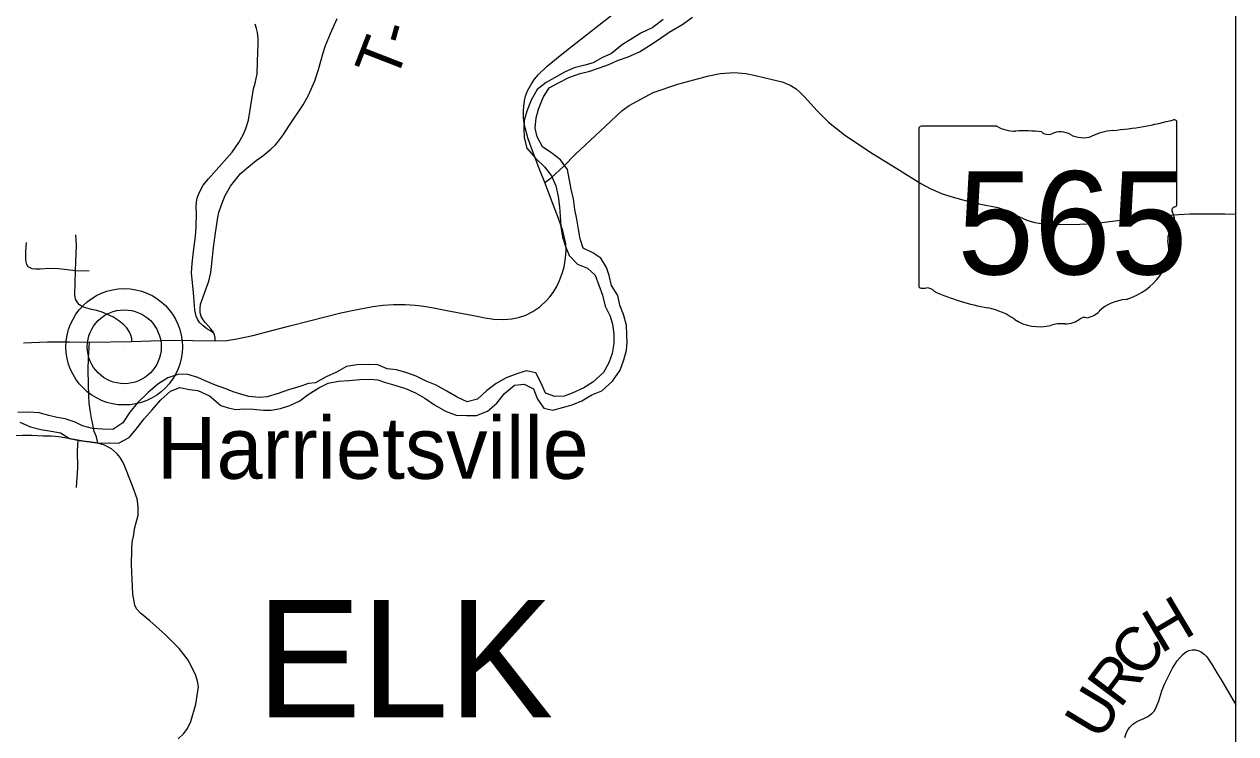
# Model space of a CAD drawing. Extents: x -10.5 to 40.6, y -3.2 to 22.
# Drawn here: x -5.292 to -3.744, y 19.035 to 19.942 of the extents above; entities that cross this region are included whole.
import ezdxf

# ---------------------------------------------------------------- set-up
doc = ezdxf.new("R2010")
doc.units = 0
for name, color, linetype in [('GM_X_County_Road', 7, 'Continuous'), ('GM_X_Major_River', 7, 'Continuous'), ('GM_X_State_Route', 7, 'Continuous'), ('GM_X_State_Shield', 7, 'Continuous'), ('GM_X_Township_Road', 7, 'Continuous'), ('GM_X_Township_Road_Text', 7, 'Continuous'), ('GM_X_Township_Text', 7, 'Continuous'), ('GM_X_Unincorporated', 7, 'Continuous'), ('GM_X_Unincorporated_Location', 7, 'Continuous'), ('GM_X_Unincorporated_Text', 7, 'Continuous')]:
    doc.layers.add(name, color=color, linetype=linetype)

msp = doc.modelspace()

# ---------------------------------------------------------------- linework, layer by layer
at = {"layer": 'GM_X_County_Road'}
msp.add_lwpolyline([(-5.0953, 19.0288), (-5.0879, 19.0354), (-5.0834, 19.042), (-5.0792, 19.0508), (-5.0727, 19.073), (-5.0694, 19.0953), (-5.0706, 19.1026), (-5.0727, 19.1098), (-5.0819, 19.1289), (-5.0941, 19.1444), (-5.1113, 19.1615), (-5.1316, 19.1794), (-5.1434, 19.1892), (-5.1486, 19.1948), (-5.1506, 19.1994), (-5.1532, 19.2136), (-5.1549, 19.2512), (-5.1546, 19.2707), (-5.1539, 19.2797), (-5.1519, 19.2898), (-5.1508, 19.2971), (-5.148, 19.3082), (-5.1462, 19.3147), (-5.1464, 19.3257), (-5.1476, 19.3356), (-5.1532, 19.3508), (-5.1618, 19.3725), (-5.165, 19.3809), (-5.1692, 19.3881), (-5.1733, 19.3931), (-5.1802, 19.3993), (-5.1893, 19.404), (-5.1978, 19.4066), (-5.1996, 19.4145), (-5.2023, 19.4214), (-5.2046, 19.4324), (-5.206, 19.4386), (-5.2078, 19.4485), (-5.2088, 19.4575), (-5.2094, 19.4669), (-5.2098, 19.4821), (-5.2103, 19.5004), (-5.2098, 19.5151), (-5.2086, 19.5357)], dxfattribs=at)
at = {"layer": 'GM_X_Major_River'}
for points in [[(-4.476, 19.9478), (-4.4891, 19.9378), (-4.5042, 19.9304), (-4.5181, 19.9219), (-4.5279, 19.9157), (-4.5418, 19.9042), (-4.5542, 19.8988), (-4.5651, 19.8926), (-4.5757, 19.8894), (-4.5896, 19.8859), (-4.602, 19.8804), (-4.6118, 19.875), (-4.6254, 19.8673), (-4.6366, 19.8585), (-4.6444, 19.8447), (-4.6499, 19.8306), (-4.6532, 19.8188), (-4.6539, 19.8086), (-4.6534, 19.7968), (-4.6498, 19.7836), (-4.6387, 19.7705), (-4.6272, 19.7596), (-4.6184, 19.7479), (-4.6129, 19.7351), (-4.6098, 19.7218), (-4.6081, 19.7086), (-4.6072, 19.6965), (-4.6063, 19.6832), (-4.6043, 19.6699), (-4.6004, 19.6578), (-4.5957, 19.6461), (-4.5854, 19.6352), (-4.5724, 19.6301), (-4.5625, 19.6211), (-4.5578, 19.6082), (-4.5531, 19.5958), (-4.55, 19.5814), (-4.5434, 19.5689), (-4.5406, 19.5587), (-4.5386, 19.5462), (-4.5388, 19.5337), (-4.541, 19.5212)], [(-4.5447, 19.6209), (-4.5482, 19.6311), (-4.5556, 19.6431), (-4.5658, 19.6499), (-4.578, 19.6558), (-4.5816, 19.6675), (-4.584, 19.68), (-4.586, 19.6929), (-4.5888, 19.705), (-4.5904, 19.7186), (-4.5932, 19.7311), (-4.598, 19.7561), (-4.6069, 19.7685), (-4.6179, 19.7771), (-4.6301, 19.7853), (-4.6367, 19.7978), (-4.6391, 19.8091), (-4.6381, 19.822), (-4.6352, 19.8334), (-4.6289, 19.8483), (-4.6215, 19.8605), (-4.6095, 19.8667), (-4.5963, 19.8737), (-4.5816, 19.8788), (-4.5695, 19.8819), (-4.5571, 19.8862), (-4.545, 19.8905), (-4.5341, 19.8956), (-4.5205, 19.9003), (-4.5062, 19.9065), (-4.4934, 19.9146), (-4.4822, 19.9219), (-4.4683, 19.9315), (-4.4521, 19.9412), (-4.4382, 19.9508)], [(-5.2973, 19.4332), (-5.2839, 19.4272), (-5.2707, 19.424), (-5.2574, 19.4218), (-5.2456, 19.4197), (-5.2338, 19.4126), (-5.2217, 19.4101), (-5.2084, 19.4083), (-5.1963, 19.4065), (-5.1842, 19.407), (-5.1713, 19.4064), (-5.1578, 19.4138), (-5.1488, 19.4245), (-5.1387, 19.4375), (-5.1283, 19.449), (-5.1174, 19.462), (-5.1051, 19.4731), (-5.093, 19.4778), (-5.0809, 19.4753), (-5.0699, 19.4739), (-5.0551, 19.4668), (-5.0409, 19.4548), (-5.0314, 19.4515), (-5.0216, 19.4494), (-5.0114, 19.4506), (-4.9989, 19.45), (-4.9864, 19.4486), (-4.9765, 19.4487), (-4.9644, 19.4507), (-4.9524, 19.4546), (-4.9399, 19.4605), (-4.9294, 19.4685), (-4.9155, 19.4774), (-4.9035, 19.4832), (-4.8906, 19.4856), (-4.8774, 19.4865), (-4.863, 19.4878), (-4.8498, 19.4883), (-4.8403, 19.4873), (-4.8305, 19.484), (-4.8183, 19.4807), (-4.805, 19.4763), (-4.7921, 19.4707), (-4.7803, 19.464), (-4.7677, 19.4555), (-4.754, 19.4476), (-4.7403, 19.4425), (-4.7271, 19.4418), (-4.7142, 19.442), (-4.7003, 19.4474), (-4.6883, 19.4578), (-4.6786, 19.47), (-4.6658, 19.4808), (-4.6533, 19.4821), (-4.6412, 19.4761), (-4.6365, 19.4629), (-4.6284, 19.4512), (-4.6166, 19.4487), (-4.6042, 19.4519), (-4.5921, 19.4554), (-4.5797, 19.4605), (-4.5669, 19.4682), (-4.5541, 19.4736), (-4.5406, 19.4859), (-4.5309, 19.5), (-4.5261, 19.513), (-4.5225, 19.5255), (-4.5218, 19.535), (-4.5223, 19.5445), (-4.5228, 19.5574), (-4.5264, 19.571), (-4.5311, 19.5827), (-4.5338, 19.5952), (-4.5416, 19.608), (-4.5447, 19.6209)], [(-4.541, 19.5212), (-4.545, 19.509), (-4.5521, 19.4968), (-4.5656, 19.4845), (-4.5772, 19.4772), (-4.5919, 19.4706), (-4.6021, 19.4667), (-4.6142, 19.4662), (-4.626, 19.4706), (-4.6314, 19.4834), (-4.6383, 19.4966), (-4.6509, 19.4988), (-4.6629, 19.4949), (-4.6765, 19.4898), (-4.6889, 19.4828), (-4.7009, 19.474), (-4.7129, 19.4629), (-4.7261, 19.4593), (-4.739, 19.4652), (-4.752, 19.4731), (-4.7657, 19.4805), (-4.7786, 19.4857), (-4.7912, 19.492), (-4.8033, 19.4964), (-4.8163, 19.5004), (-4.8284, 19.5015), (-4.8402, 19.5066), (-4.8527, 19.5069), (-4.867, 19.5064), (-4.8802, 19.5043), (-4.893, 19.4974), (-4.9062, 19.4912), (-4.9198, 19.4838), (-4.9288, 19.4826), (-4.9409, 19.4783), (-4.9541, 19.4747), (-4.9673, 19.47), (-4.9816, 19.4657), (-4.9915, 19.4648), (-5.0051, 19.4662), (-5.0153, 19.4691), (-5.0248, 19.4721), (-5.0343, 19.4758), (-5.0476, 19.4806), (-5.0606, 19.4861), (-5.0701, 19.4906), (-5.083, 19.4942), (-5.0943, 19.4945), (-5.1083, 19.4901), (-5.1211, 19.482), (-5.1334, 19.4713), (-5.1473, 19.4579), (-5.157, 19.446), (-5.1659, 19.4326), (-5.1787, 19.4242), (-5.192, 19.4244), (-5.2045, 19.4254), (-5.2174, 19.4287), (-5.2269, 19.4335), (-5.2394, 19.4376), (-5.2496, 19.4393), (-5.2606, 19.4419), (-5.2728, 19.4452), (-5.286, 19.4462), (-5.3, 19.4456)]]:
    msp.add_lwpolyline(points, dxfattribs=at)
at = {"layer": 'GM_X_State_Route'}
for points in [[(-4.6269, 19.7394), (-4.6334, 19.7552), (-4.6439, 19.7833), (-4.6487, 19.7967), (-4.6525, 19.811), (-4.6534, 19.8155), (-4.6541, 19.8222), (-4.6541, 19.8313), (-4.6539, 19.8368), (-4.6527, 19.844), (-4.6515, 19.8497), (-4.649, 19.8567), (-4.6441, 19.8655), (-4.64, 19.8717), (-4.6352, 19.8777), (-4.6238, 19.8883), (-4.6072, 19.9018), (-4.5814, 19.9221), (-4.5285, 19.9635)], [(-4.6269, 19.7394), (-4.6187, 19.7456), (-4.6025, 19.7606), (-4.5884, 19.7754), (-4.5494, 19.8115), (-4.5288, 19.831), (-4.5193, 19.8378), (-4.4886, 19.8544), (-4.456, 19.8655), (-4.4175, 19.8757), (-4.4032, 19.879), (-4.385, 19.8802), (-4.3703, 19.8788), (-4.3579, 19.8763), (-4.3366, 19.8713), (-4.324, 19.868), (-4.3136, 19.8641), (-4.3058, 19.8592), (-4.3011, 19.8548), (-4.2954, 19.8489), (-4.2791, 19.831), (-4.2646, 19.8167), (-4.2441, 19.8004), (-4.2118, 19.7786), (-4.1738, 19.7553), (-4.1466, 19.7381), (-4.135, 19.7318), (-4.1205, 19.7255), (-4.1084, 19.7215), (-4.093, 19.7173), (-4.0785, 19.7137), (-4.0637, 19.7108), (-4.0547, 19.7091), (-4.0485, 19.7075), (-4.0394, 19.7046), (-4.0305, 19.7008), (-4.0205, 19.6955), (-4.0113, 19.6915), (-4.0011, 19.6886), (-3.9955, 19.6876), (-3.9879, 19.6868), (-3.9689, 19.6859), (-3.9438, 19.6863), (-3.9253, 19.6872), (-3.8887, 19.692), (-3.8621, 19.6951), (-3.8415, 19.697), (-3.8173, 19.6987), (-3.8033, 19.6994), (-3.784, 19.6996), (-3.7584, 19.6996), (-3.7445, 19.6989)], [(-5.2927, 19.5347), (-5.2623, 19.5358), (-5.234, 19.5358), (-5.2086, 19.5357), (-5.1542, 19.5363), (-5.1057, 19.5381), (-5.0478, 19.5374), (-5.033, 19.5379), (-5.0204, 19.5397), (-4.9997, 19.544), (-4.9739, 19.5507), (-4.9528, 19.5564), (-4.9059, 19.5683), (-4.8873, 19.5729), (-4.8668, 19.5775), (-4.8464, 19.5811), (-4.8332, 19.5827), (-4.8201, 19.5835), (-4.8053, 19.5835), (-4.7927, 19.5827), (-4.7815, 19.5814), (-4.7691, 19.5793), (-4.7523, 19.5761), (-4.7114, 19.5682), (-4.7035, 19.5666), (-4.6919, 19.565), (-4.6791, 19.5645), (-4.669, 19.5654), (-4.6604, 19.5671), (-4.651, 19.5702), (-4.6421, 19.5746), (-4.6332, 19.5806), (-4.6248, 19.5887), (-4.6204, 19.5936), (-4.6162, 19.5989), (-4.6116, 19.6067), (-4.6081, 19.6142), (-4.6044, 19.6245), (-4.6024, 19.6318), (-4.6005, 19.6428), (-4.5997, 19.6532), (-4.6003, 19.6614), (-4.6016, 19.6689), (-4.6038, 19.6776), (-4.6082, 19.6903), (-4.6172, 19.7135), (-4.6269, 19.7394)]]:
    msp.add_lwpolyline(points, dxfattribs=at)
at = {"layer": 'GM_X_State_Shield'}
for p, q in [((-4.1493, 19.8081), (-4.1493, 19.6079)), ((-4.0495, 19.8115), (-4.146, 19.8115)), ((-3.8197, 19.7118), (-3.8197, 19.8165)), ((-3.8197, 19.7118), (-3.8197, 19.7118))]:
    msp.add_line(p, q, dxfattribs=at)
for centre, major_axis, start_param, end_param in [((-4.1455, 19.8085), (0.00382, 0), 1.712693, 3.28349), ((-4.0265, 19.8347), (0.037, 0), 4.042523, 4.731795), ((-3.8925, 19.7504), (0.0703, 0), 1.699011, 2.107814), ((-3.9371, 20.0843), (0.3495, 0), 4.814394, 5.042369), ((-3.8234, 19.8169), (0.00367, 0), 6.141152, 7.989035), ((-4.0143, 19.6992), (0.133, 0), 1.404758, 1.657858), ((-3.9841, 19.8095), (0.0107, 0), 3.836095, 5.185415), ((-3.9684, 19.7864), (0.0222, 0), 0.950623, 2.079405), ((-3.9397, 19.8181), (0.0267, 0), 4.081561, 5.145723), ((-3.8206, 19.7041), (0.00568, 0), 1.883978, 3.671073), ((-3.8567, 19.6909), (0.0341, 0), 5.934695, 6.695948), ((-3.8236, 19.7114), (0.00393, 0), 5.05454, 6.418171), ((-3.8066, 19.668), (0.0248, 0), 2.387724, 3.262537), ((-3.9175, 19.6547), (0.0874, 0), 5.101752, 6.440018), ((-4.1455, 19.6075), (0.00385, 0), 3.00124, 4.508301), ((-4.1449, 19.628), (0.0294, 0), 4.665946, 4.897461), ((-4.1389, 19.5964), (0.0106, 0), 0.519207, 1.627899), ((-4.0051, 19.7762), (0.2524, 0), 4.195997, 4.488961), ((-3.8807, 19.5518), (0.0479, 0), 1.647645, 2.488434), ((-4.0803, 19.518), (0.079, 0), 0.823519, 1.323587), ((-3.9413, 19.5886), (0.0282, 0), 4.937069, 5.64225), ((-3.9949, 19.5954), (0.0501, 0), 4.026481, 4.996735), ((-3.9659, 19.5262), (0.0412, 0), 1.495662, 1.94098), ((-3.9623, 19.5804), (0.0267, 0), 4.691044, 5.507374), ((-3.9381, 19.561), (0.00752, 0), 1.147584, 2.315152)]:
    msp.add_ellipse(centre, major_axis=major_axis, ratio=0.8, start_param=start_param, end_param=end_param, dxfattribs=at)
at = {"layer": 'GM_X_Township_Road'}
for points in [[(-5.0478, 19.5374), (-5.048, 19.5409), (-5.049, 19.5451), (-5.0497, 19.547), (-5.0508, 19.5493), (-5.0533, 19.5525), (-5.0568, 19.5564), (-5.0606, 19.5606), (-5.0633, 19.5639), (-5.0659, 19.5683), (-5.067, 19.5732), (-5.0672, 19.5786), (-5.0665, 19.5843), (-5.0561, 19.6137), (-5.0547, 19.6191), (-5.0537, 19.6244), (-5.0521, 19.6361), (-5.0499, 19.6567), (-5.0474, 19.6751), (-5.0444, 19.6949), (-5.0431, 19.7013), (-5.0395, 19.7124), (-5.0352, 19.7228), (-5.0283, 19.7348), (-5.0237, 19.741), (-5.0185, 19.7474), (-5.0159, 19.7505), (-5.0075, 19.758), (-4.9956, 19.7676), (-4.9915, 19.7706), (-4.987, 19.7737), (-4.9769, 19.7822), (-4.9708, 19.7877), (-4.9682, 19.7905), (-4.9657, 19.7939), (-4.9605, 19.8007), (-4.954, 19.8117), (-4.9356, 19.8388), (-4.9287, 19.8513), (-4.9208, 19.8696), (-4.916, 19.8838), (-4.9101, 19.9051), (-4.907, 19.9145), (-4.9005, 19.9298), (-4.892, 19.9492)], [(-5.0497, 19.547), (-5.0541, 19.5499), (-5.0587, 19.5527), (-5.0639, 19.557), (-5.0678, 19.5609), (-5.0705, 19.5648), (-5.0723, 19.5686), (-5.074, 19.5766), (-5.0746, 19.5883), (-5.0756, 19.5986), (-5.0771, 19.6116), (-5.0781, 19.6236), (-5.0772, 19.636), (-5.0758, 19.6515), (-5.0732, 19.6708), (-5.0721, 19.6829), (-5.0719, 19.7006), (-5.0721, 19.7076), (-5.0717, 19.7148), (-5.0708, 19.7195), (-5.0694, 19.7241), (-5.0669, 19.7296), (-5.0631, 19.736), (-5.0564, 19.7442), (-5.0467, 19.7552), (-5.0262, 19.7782), (-5.0176, 19.7907), (-5.0123, 19.8004), (-5.0089, 19.8086), (-5.0055, 19.8194), (-4.999, 19.8591), (-4.9969, 19.8664), (-4.9943, 19.8785), (-4.9933, 19.907), (-4.993, 19.9147), (-4.9931, 19.9233), (-4.9941, 19.931), (-4.9952, 19.9362), (-4.997, 19.942)], [(-5.1542, 19.5363), (-5.1546, 19.5402), (-5.1558, 19.5447), (-5.1577, 19.5491), (-5.1606, 19.5537), (-5.1646, 19.5577), (-5.1709, 19.563), (-5.1788, 19.5681), (-5.1924, 19.5737), (-5.1992, 19.5759), (-5.2059, 19.5772), (-5.212, 19.5788), (-5.2173, 19.5808), (-5.2214, 19.5831), (-5.224, 19.5861), (-5.2262, 19.5904), (-5.227, 19.5962), (-5.2264, 19.6265), (-5.2253, 19.6487), (-5.225, 19.6589), (-5.2259, 19.6729)], [(-5.2091, 19.6263), (-5.2264, 19.6265), (-5.2475, 19.6294), (-5.2592, 19.6296), (-5.2714, 19.629), (-5.2774, 19.6287), (-5.2816, 19.6293), (-5.2869, 19.6319), (-5.2884, 19.6348), (-5.2896, 19.6397), (-5.2898, 19.6516), (-5.2895, 19.6573), (-5.2889, 19.663)], [(-5.1978, 19.4066), (-5.2061, 19.4076), (-5.2166, 19.4092), (-5.2232, 19.4105), (-5.2478, 19.4145), (-5.2572, 19.4153), (-5.2675, 19.4156), (-5.2823, 19.4165), (-5.2939, 19.4163), (-5.3049, 19.416), (-5.3211, 19.4157), (-5.3365, 19.4196), (-5.3447, 19.421), (-5.3514, 19.4207), (-5.3595, 19.4182), (-5.3693, 19.4132), (-5.3755, 19.4086), (-5.3795, 19.4048), (-5.3852, 19.3962), (-5.3883, 19.3887), (-5.3924, 19.3769), (-5.3935, 19.3711), (-5.3935, 19.3644), (-5.3912, 19.3577)], [(-5.2232, 19.4105), (-5.2241, 19.3966), (-5.2239, 19.3751), (-5.2253, 19.3498)], [(-3.886, 19.0306), (-3.8846, 19.0356), (-3.8827, 19.0396), (-3.8797, 19.0435), (-3.8759, 19.0474), (-3.8707, 19.0508), (-3.862, 19.0549), (-3.8568, 19.0574), (-3.8515, 19.061), (-3.8487, 19.0642), (-3.8464, 19.0681), (-3.8448, 19.0722), (-3.8427, 19.0774), (-3.8389, 19.0902), (-3.8356, 19.0986), (-3.8309, 19.1082), (-3.8255, 19.1189), (-3.8192, 19.1285), (-3.812, 19.1366), (-3.8076, 19.1403), (-3.8039, 19.1417), (-3.8, 19.1426), (-3.7961, 19.1426), (-3.7918, 19.1414), (-3.7883, 19.1395), (-3.785, 19.137), (-3.7816, 19.1334), (-3.7748, 19.1234), (-3.7687, 19.1131), (-3.7623, 19.1027), (-3.7521, 19.0855), (-3.7445, 19.0722)]]:
    msp.add_lwpolyline(points, dxfattribs=at)
at = {"layer": 'GM_X_Township_Text'}
msp.add_lwpolyline([(-3.7445, 16.8499), (-3.7445, 20.9), (-6.1618, 20.9)], dxfattribs=at)
at = {"layer": 'GM_X_Unincorporated'}
for radius in [0.0744, 0.0472]:
    msp.add_circle((-5.1641, 19.5297), radius, dxfattribs=at)
at = {"layer": 'GM_X_Unincorporated_Location'}
msp.add_line((-5.1641, 19.5297), (-5.1641, 19.5297), dxfattribs=at)

# ---------------------------------------------------------------- texts
at = {"layer": 'GM_X_State_Shield'}
msp.add_text('565', height=0.13184, dxfattribs=at).set_placement((-4.1002, 19.6221))
at = {"layer": 'GM_X_Township_Road_Text'}
for s, rotation, p in [('-', 74.2632, (-4.8005, 19.9126)), ('T', 68.7979, (-4.8177, 19.8674)), ('H', 30.762, (-3.8402, 19.137)), ('C', 52.7593, (-3.8642, 19.1036)), ('R', 53.0911, (-3.8922, 19.0664)), ('U', 58.8163, (-3.9172, 19.0248))]:
    msp.add_text(s, height=0.0568, rotation=rotation, dxfattribs=at).set_placement(p)
at = {"layer": 'GM_X_Township_Text'}
msp.add_text('ELK', height=0.15, rotation=0, dxfattribs=at).set_placement((-4.9953, 19.0563))
at = {"layer": 'GM_X_Unincorporated_Text'}
msp.add_text('Harrietsville', height=0.078977, rotation=0, dxfattribs=at).set_placement((-5.1225, 19.361))

doc.saveas('drawing.dxf')
